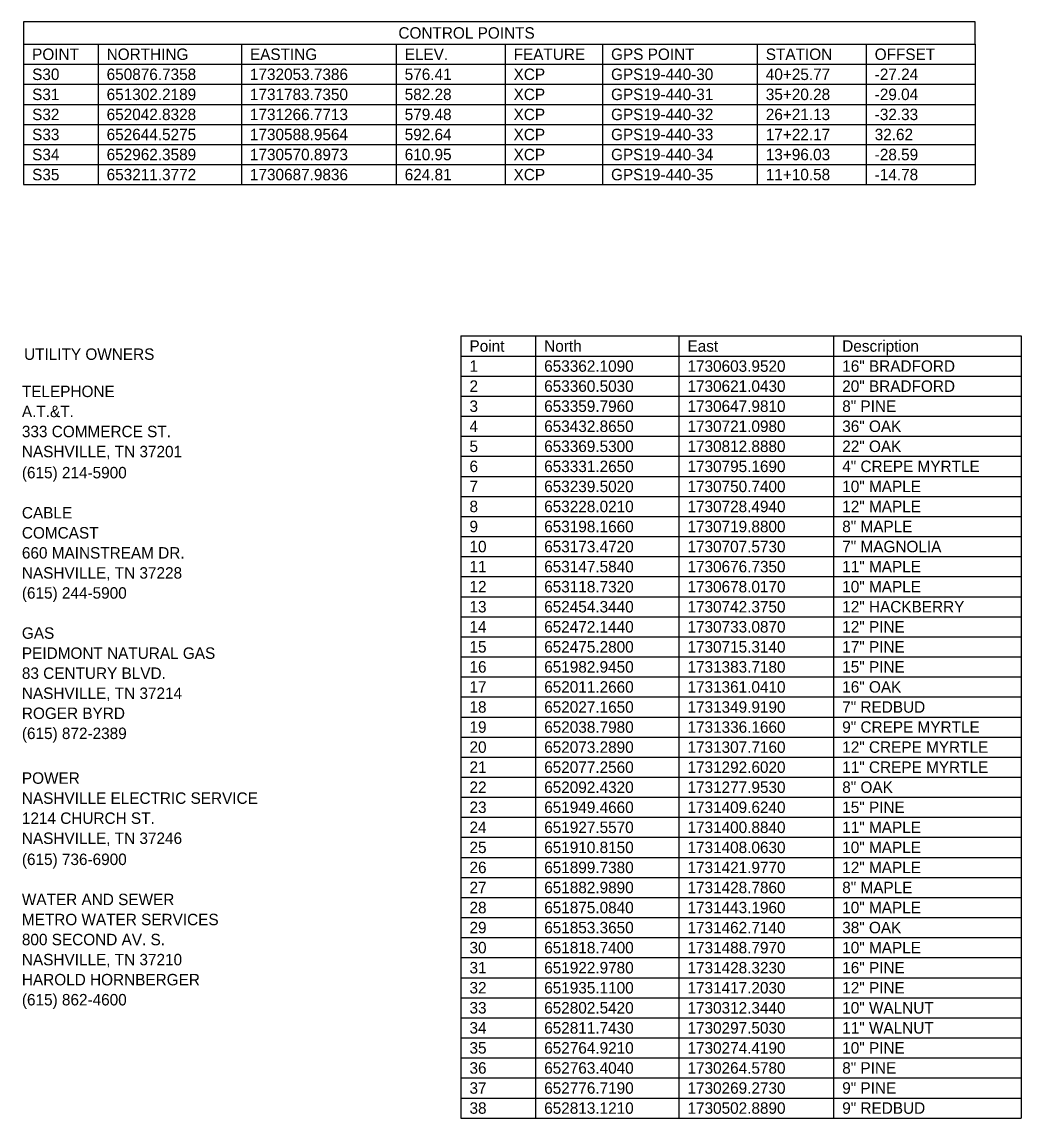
# Model space of a CAD drawing. Extents: x 1729869 to 1735532, y 648588 to 653771.
# Drawn here: x 1732635.3 to 1733071.1, y 650464.1 to 650942.4 of the extents above; entities that cross this region are included whole.
import ezdxf

# ---------------------------------------------------------------- set-up
doc = ezdxf.new("R2010")
doc.units = 0
for name, color, linetype in [('SURVEY - CONTROL with Text', 7, 'Continuous'), ('SURVEY - UTILITIES - Owners', 7, 'Continuous'), ('SURVEY - VEGETATION - Features with Text', 7, 'Continuous')]:
    doc.layers.add(name, color=color, linetype=linetype)

msp = doc.modelspace()

# ---------------------------------------------------------------- linework, layer by layer
at = {"layer": 'SURVEY - CONTROL with Text'}
for p, q in [((1732636.01, 650932.65), (1733051.01, 650932.65)), ((1732636.01, 650932.65), (1732636.01, 650871.4)), ((1732668.51, 650932.65), (1732668.51, 650871.4)), ((1732731.01, 650932.65), (1732731.01, 650871.4)), ((1732798.51, 650932.65), (1732798.51, 650871.4)), ((1732846.01, 650932.65), (1732846.01, 650871.4)), ((1732888.51, 650932.65), (1732888.51, 650871.4)), ((1732956.01, 650932.65), (1732956.01, 650871.4)), ((1733003.51, 650932.65), (1733003.51, 650871.4)), ((1733051.01, 650932.65), (1733051.01, 650871.4)), ((1732636.01, 650923.9), (1733051.01, 650923.9)), ((1732636.01, 650915.15), (1733051.01, 650915.15)), ((1732636.01, 650915.15), (1733051.01, 650915.15)), ((1732636.01, 650915.15), (1733051.01, 650915.15)), ((1732636.01, 650915.15), (1733051.01, 650915.15)), ((1732636.01, 650915.15), (1733051.01, 650915.15)), ((1732636.01, 650915.15), (1733051.01, 650915.15)), ((1732636.01, 650915.15), (1733051.01, 650915.15)), ((1732636.01, 650915.15), (1733051.01, 650915.15)), ((1732636.01, 650906.4), (1733051.01, 650906.4)), ((1732636.01, 650906.4), (1733051.01, 650906.4)), ((1732636.01, 650906.4), (1733051.01, 650906.4)), ((1732636.01, 650906.4), (1733051.01, 650906.4)), ((1732636.01, 650906.4), (1733051.01, 650906.4)), ((1732636.01, 650906.4), (1733051.01, 650906.4)), ((1732636.01, 650906.4), (1733051.01, 650906.4)), ((1732636.01, 650906.4), (1733051.01, 650906.4)), ((1732636.01, 650897.65), (1733051.01, 650897.65)), ((1732636.01, 650897.65), (1733051.01, 650897.65)), ((1732636.01, 650897.65), (1733051.01, 650897.65)), ((1732636.01, 650897.65), (1733051.01, 650897.65)), ((1732636.01, 650897.65), (1733051.01, 650897.65)), ((1732636.01, 650897.65), (1733051.01, 650897.65)), ((1732636.01, 650897.65), (1733051.01, 650897.65)), ((1732636.01, 650897.65), (1733051.01, 650897.65)), ((1732636.01, 650888.9), (1733051.01, 650888.9)), ((1732636.01, 650888.9), (1733051.01, 650888.9)), ((1732636.01, 650888.9), (1733051.01, 650888.9)), ((1732636.01, 650888.9), (1733051.01, 650888.9)), ((1732636.01, 650888.9), (1733051.01, 650888.9)), ((1732636.01, 650888.9), (1733051.01, 650888.9)), ((1732636.01, 650888.9), (1733051.01, 650888.9)), ((1732636.01, 650888.9), (1733051.01, 650888.9)), ((1732636.01, 650880.15), (1733051.01, 650880.15)), ((1732636.01, 650880.15), (1733051.01, 650880.15)), ((1732636.01, 650880.15), (1733051.01, 650880.15)), ((1732636.01, 650880.15), (1733051.01, 650880.15)), ((1732636.01, 650880.15), (1733051.01, 650880.15)), ((1732636.01, 650880.15), (1733051.01, 650880.15)), ((1732636.01, 650880.15), (1733051.01, 650880.15)), ((1732636.01, 650880.15), (1733051.01, 650880.15)), ((1732636.01, 650871.4), (1733051.01, 650871.4)), ((1732636.01, 650871.4), (1733051.01, 650871.4)), ((1732636.01, 650871.4), (1733051.01, 650871.4)), ((1732636.01, 650871.4), (1733051.01, 650871.4)), ((1732636.01, 650871.4), (1733051.01, 650871.4)), ((1732636.01, 650871.4), (1733051.01, 650871.4)), ((1732636.01, 650871.4), (1733051.01, 650871.4)), ((1732636.01, 650871.4), (1733051.01, 650871.4))]:
    msp.add_line(p, q, dxfattribs=at)
msp.add_lwpolyline([(1732636.01, 650932.65), (1733051.01, 650932.65), (1733051.01, 650942.38), (1732636.01, 650942.38)], close=True, dxfattribs=at)
at = {"layer": 'SURVEY - VEGETATION - Features with Text'}
for p, q in [((1732826.77, 650805.34), (1733071.1, 650805.34)), ((1732826.77, 650805.34), (1732826.77, 650464.09)), ((1732859.35, 650805.34), (1732859.35, 650464.09)), ((1732921.85, 650805.34), (1732921.85, 650464.09)), ((1732989.35, 650805.34), (1732989.35, 650464.09)), ((1733071.1, 650805.34), (1733071.1, 650464.09)), ((1732826.77, 650796.59), (1733071.1, 650796.59)), ((1732826.77, 650787.84), (1733056.77, 650787.84)), ((1732826.77, 650787.84), (1733056.77, 650787.84)), ((1732826.77, 650787.84), (1733056.77, 650787.84)), ((1732826.77, 650787.84), (1733071.1, 650787.84)), ((1732826.77, 650779.09), (1733056.77, 650779.09)), ((1732826.77, 650779.09), (1733056.77, 650779.09)), ((1732826.77, 650779.09), (1733056.77, 650779.09)), ((1732826.77, 650779.09), (1733071.1, 650779.09)), ((1732826.77, 650770.34), (1733056.77, 650770.34)), ((1732826.77, 650770.34), (1733056.77, 650770.34)), ((1732826.77, 650770.34), (1733056.77, 650770.34)), ((1732826.77, 650770.34), (1733071.1, 650770.34)), ((1732826.77, 650761.59), (1733056.77, 650761.59)), ((1732826.77, 650761.59), (1733056.77, 650761.59)), ((1732826.77, 650761.59), (1733056.77, 650761.59)), ((1732826.77, 650761.59), (1733071.1, 650761.59)), ((1732826.77, 650752.84), (1733056.77, 650752.84)), ((1732826.77, 650752.84), (1733056.77, 650752.84)), ((1732826.77, 650752.84), (1733056.77, 650752.84)), ((1732826.77, 650752.84), (1733071.1, 650752.84)), ((1732826.77, 650744.09), (1733056.77, 650744.09)), ((1732826.77, 650744.09), (1733056.77, 650744.09)), ((1732826.77, 650744.09), (1733056.77, 650744.09)), ((1732826.77, 650744.09), (1733071.1, 650744.09)), ((1732826.77, 650735.34), (1733056.77, 650735.34)), ((1732826.77, 650735.34), (1733056.77, 650735.34)), ((1732826.77, 650735.34), (1733056.77, 650735.34)), ((1732826.77, 650735.34), (1733071.1, 650735.34)), ((1732826.77, 650726.59), (1733056.77, 650726.59)), ((1732826.77, 650726.59), (1733056.77, 650726.59)), ((1732826.77, 650726.59), (1733056.77, 650726.59)), ((1732826.77, 650726.59), (1733071.1, 650726.59)), ((1732826.77, 650717.84), (1733056.77, 650717.84)), ((1732826.77, 650717.84), (1733056.77, 650717.84)), ((1732826.77, 650717.84), (1733071.1, 650717.84)), ((1732826.77, 650709.09), (1733056.77, 650709.09)), ((1732826.77, 650709.09), (1733056.77, 650709.09)), ((1732826.77, 650709.09), (1733056.77, 650709.09)), ((1732826.77, 650709.09), (1733071.1, 650709.09)), ((1732826.77, 650700.34), (1733056.77, 650700.34)), ((1732826.77, 650700.34), (1733056.77, 650700.34)), ((1732826.77, 650700.34), (1733056.77, 650700.34)), ((1732826.77, 650700.34), (1733071.1, 650700.34)), ((1732826.77, 650691.59), (1733056.77, 650691.59)), ((1732826.77, 650691.59), (1733056.77, 650691.59)), ((1732826.77, 650691.59), (1733056.77, 650691.59)), ((1732826.77, 650691.59), (1733071.1, 650691.59)), ((1732826.77, 650682.84), (1733056.77, 650682.84)), ((1732826.77, 650682.84), (1733056.77, 650682.84)), ((1732826.77, 650682.84), (1733056.77, 650682.84)), ((1732826.77, 650682.84), (1733071.1, 650682.84)), ((1732826.77, 650674.09), (1733056.77, 650674.09)), ((1732826.77, 650674.09), (1733056.77, 650674.09)), ((1732826.77, 650674.09), (1733056.77, 650674.09)), ((1732826.77, 650674.09), (1733071.1, 650674.09)), ((1732826.77, 650665.34), (1733056.77, 650665.34)), ((1732826.77, 650665.34), (1733056.77, 650665.34)), ((1732826.77, 650665.34), (1733056.77, 650665.34)), ((1732826.77, 650665.34), (1733071.1, 650665.34)), ((1732826.77, 650656.59), (1733056.77, 650656.59)), ((1732826.77, 650656.59), (1733056.77, 650656.59)), ((1732826.77, 650656.59), (1733056.77, 650656.59)), ((1732826.77, 650656.59), (1733071.1, 650656.59)), ((1732826.77, 650647.84), (1733056.77, 650647.84)), ((1732826.77, 650647.84), (1733056.77, 650647.84)), ((1732826.77, 650647.84), (1733056.77, 650647.84)), ((1732826.77, 650647.84), (1733071.1, 650647.84)), ((1732826.77, 650639.09), (1733056.77, 650639.09)), ((1732826.77, 650639.09), (1733056.77, 650639.09)), ((1732826.77, 650639.09), (1733056.77, 650639.09)), ((1732826.77, 650639.09), (1733071.1, 650639.09)), ((1732826.77, 650630.34), (1733056.77, 650630.34)), ((1732826.77, 650630.34), (1733056.77, 650630.34)), ((1732826.77, 650630.34), (1733056.77, 650630.34)), ((1732826.77, 650630.34), (1733071.1, 650630.34)), ((1732826.77, 650621.59), (1733056.77, 650621.59)), ((1732826.77, 650621.59), (1733056.77, 650621.59)), ((1732826.77, 650621.59), (1733056.77, 650621.59)), ((1732826.77, 650621.59), (1733071.1, 650621.59)), ((1732826.77, 650612.84), (1733056.77, 650612.84)), ((1732826.77, 650612.84), (1733056.77, 650612.84)), ((1732826.77, 650612.84), (1733056.77, 650612.84)), ((1732826.77, 650612.84), (1733071.1, 650612.84)), ((1732826.77, 650604.09), (1733056.77, 650604.09)), ((1732826.77, 650604.09), (1733056.77, 650604.09)), ((1732826.77, 650604.09), (1733056.77, 650604.09)), ((1732826.77, 650604.09), (1733071.1, 650604.09)), ((1732826.77, 650595.34), (1733056.77, 650595.34)), ((1732826.77, 650595.34), (1733056.77, 650595.34)), ((1732826.77, 650595.34), (1733056.77, 650595.34)), ((1732826.77, 650595.34), (1733071.1, 650595.34)), ((1732826.77, 650586.59), (1733056.77, 650586.59)), ((1732826.77, 650586.59), (1733056.77, 650586.59)), ((1732826.77, 650586.59), (1733056.77, 650586.59)), ((1732826.77, 650586.59), (1733071.1, 650586.59)), ((1732826.77, 650577.84), (1733056.77, 650577.84)), ((1732826.77, 650577.84), (1733056.77, 650577.84)), ((1732826.77, 650577.84), (1733056.77, 650577.84)), ((1732826.77, 650577.84), (1733071.1, 650577.84)), ((1732826.77, 650569.09), (1733056.77, 650569.09)), ((1732826.77, 650569.09), (1733056.77, 650569.09)), ((1732826.77, 650569.09), (1733056.77, 650569.09)), ((1732826.77, 650569.09), (1733071.1, 650569.09)), ((1732826.77, 650560.34), (1733056.77, 650560.34)), ((1732826.77, 650560.34), (1733056.77, 650560.34)), ((1732826.77, 650560.34), (1733056.77, 650560.34)), ((1732826.77, 650560.34), (1733071.1, 650560.34)), ((1732826.77, 650551.59), (1733056.77, 650551.59)), ((1732826.77, 650551.59), (1733056.77, 650551.59)), ((1732826.77, 650551.59), (1733056.77, 650551.59)), ((1732826.77, 650551.59), (1733071.1, 650551.59)), ((1732826.77, 650542.84), (1733056.77, 650542.84)), ((1732826.77, 650542.84), (1733056.77, 650542.84)), ((1732826.77, 650542.84), (1733056.77, 650542.84)), ((1732826.77, 650542.84), (1733071.1, 650542.84)), ((1732826.77, 650534.09), (1733056.77, 650534.09)), ((1732826.77, 650534.09), (1733056.77, 650534.09)), ((1732826.77, 650534.09), (1733056.77, 650534.09)), ((1732826.77, 650534.09), (1733071.1, 650534.09)), ((1732826.77, 650525.34), (1733056.77, 650525.34)), ((1732826.77, 650525.34), (1733056.77, 650525.34)), ((1732826.77, 650525.34), (1733056.77, 650525.34)), ((1732826.77, 650525.34), (1733071.1, 650525.34)), ((1732826.77, 650516.59), (1733056.77, 650516.59)), ((1732826.77, 650516.59), (1733056.77, 650516.59)), ((1732826.77, 650516.59), (1733056.77, 650516.59)), ((1732826.77, 650516.59), (1733071.1, 650516.59)), ((1732826.77, 650507.84), (1733056.77, 650507.84)), ((1732826.77, 650507.84), (1733056.77, 650507.84)), ((1732826.77, 650507.84), (1733056.77, 650507.84)), ((1732826.77, 650507.84), (1733071.1, 650507.84)), ((1732826.77, 650499.09), (1733056.77, 650499.09)), ((1732826.77, 650499.09), (1733056.77, 650499.09)), ((1732826.77, 650499.09), (1733056.77, 650499.09)), ((1732826.77, 650499.09), (1733071.1, 650499.09)), ((1732826.77, 650490.34), (1733056.77, 650490.34)), ((1732826.77, 650490.34), (1733056.77, 650490.34)), ((1732826.77, 650490.34), (1733056.77, 650490.34)), ((1732826.77, 650490.34), (1733071.1, 650490.34)), ((1732826.77, 650481.59), (1733056.77, 650481.59)), ((1732826.77, 650481.59), (1733056.77, 650481.59)), ((1732826.77, 650481.59), (1733056.77, 650481.59)), ((1732826.77, 650481.59), (1733071.1, 650481.59)), ((1732826.77, 650472.84), (1733056.77, 650472.84)), ((1732826.77, 650472.84), (1733056.77, 650472.84)), ((1732826.77, 650472.84), (1733056.77, 650472.84)), ((1732826.77, 650472.84), (1733071.1, 650472.84)), ((1732826.77, 650464.09), (1733056.77, 650464.09)), ((1732826.77, 650464.09), (1733056.77, 650464.09)), ((1732826.77, 650464.09), (1733056.77, 650464.09)), ((1732826.77, 650464.09), (1733071.1, 650464.09))]:
    msp.add_line(p, q, dxfattribs=at)

# ---------------------------------------------------------------- texts
at = {"layer": 'SURVEY - CONTROL with Text'}
for s, p in [('CONTROL POINTS', (1732799.52, 650935.07)), ('POINT', (1732639.76, 650925.77)), ('NORTHING', (1732672.26, 650925.77)), ('EASTING', (1732734.76, 650925.77)), ('ELEV.', (1732802.26, 650925.77)), ('FEATURE', (1732849.76, 650925.77)), ('GPS POINT', (1732892.26, 650925.77)), ('STATION', (1732959.76, 650925.77)), ('OFFSET', (1733007.26, 650925.77)), ('S30', (1732639.76, 650917.02)), ('650876.7358', (1732672.26, 650917.02)), ('1732053.7386', (1732734.76, 650917.02)), ('576.41', (1732802.26, 650917.02)), ('XCP', (1732849.76, 650917.02)), ('GPS19-440-30', (1732892.26, 650917.02)), ('40+25.77', (1732959.76, 650917.02)), ('-27.24', (1733007.26, 650917.02)), ('S31', (1732639.76, 650908.27)), ('651302.2189', (1732672.26, 650908.27)), ('1731783.7350', (1732734.76, 650908.27)), ('582.28', (1732802.26, 650908.27)), ('XCP', (1732849.76, 650908.27)), ('GPS19-440-31', (1732892.26, 650908.27)), ('35+20.28', (1732959.76, 650908.27)), ('-29.04', (1733007.26, 650908.27)), ('S32', (1732639.76, 650899.52)), ('652042.8328', (1732672.26, 650899.52)), ('1731266.7713', (1732734.76, 650899.52)), ('579.48', (1732802.26, 650899.52)), ('XCP', (1732849.76, 650899.52)), ('GPS19-440-32', (1732892.26, 650899.52)), ('26+21.13', (1732959.76, 650899.52)), ('-32.33', (1733007.26, 650899.52)), ('S33', (1732639.76, 650890.77)), ('652644.5275', (1732672.26, 650890.77)), ('1730588.9564', (1732734.76, 650890.77)), ('592.64', (1732802.26, 650890.77)), ('XCP', (1732849.76, 650890.77)), ('GPS19-440-33', (1732892.26, 650890.77)), ('17+22.17', (1732959.76, 650890.77)), ('32.62', (1733007.26, 650890.77)), ('S34', (1732639.76, 650882.02)), ('652962.3589', (1732672.26, 650882.02)), ('1730570.8973', (1732734.76, 650882.02)), ('610.95', (1732802.26, 650882.02)), ('XCP', (1732849.76, 650882.02)), ('GPS19-440-34', (1732892.26, 650882.02)), ('13+96.03', (1732959.76, 650882.02)), ('-28.59', (1733007.26, 650882.02)), ('S35', (1732639.76, 650873.27)), ('653211.3772', (1732672.26, 650873.27)), ('1730687.9836', (1732734.76, 650873.27)), ('624.81', (1732802.26, 650873.27)), ('XCP', (1732849.76, 650873.27)), ('GPS19-440-35', (1732892.26, 650873.27)), ('11+10.58', (1732959.76, 650873.27)), ('-14.78', (1733007.26, 650873.27))]:
    msp.add_text(s, height=5, dxfattribs=at).set_placement(p)
at = {"layer": 'SURVEY - UTILITIES - Owners'}
for s, p in [('UTILITY OWNERS', (1732636.24, 650794.91)), ('TELEPHONE', (1732635.29, 650778.67)), ('A.T.&T.', (1732635.29, 650769.92)), ('333 COMMERCE ST.', (1732635.29, 650761.17)), ('NASHVILLE, TN 37201', (1732635.29, 650752.42)), ('(615) 214-5900', (1732635.29, 650743.21)), ('CABLE', (1732635.29, 650725.71)), ('COMCAST', (1732635.29, 650716.96)), ('660 MAINSTREAM DR.', (1732635.29, 650708.21)), ('NASHVILLE, TN 37228', (1732635.29, 650699.46)), ('(615) 244-5900', (1732635.29, 650690.71)), ('GAS', (1732635.29, 650673.21)), ('PEIDMONT NATURAL GAS', (1732635.29, 650664.46)), ('83 CENTURY BLVD.', (1732635.29, 650655.71)), ('NASHVILLE, TN 37214', (1732635.29, 650646.96)), ('ROGER BYRD', (1732635.29, 650638.21)), ('(615) 872-2389', (1732635.29, 650629.46)), ('POWER', (1732635.29, 650609.94)), ('NASHVILLE ELECTRIC SERVICE', (1732635.29, 650601.19)), ('1214 CHURCH ST.', (1732635.29, 650592.44)), ('NASHVILLE, TN 37246', (1732635.29, 650583.69)), ('(615) 736-6900', (1732635.29, 650574.49)), ('WATER AND SEWER', (1732635.29, 650556.99)), ('METRO WATER SERVICES', (1732635.29, 650548.24)), ('800 SECOND AV. S.', (1732635.29, 650539.49)), ('NASHVILLE, TN 37210', (1732635.29, 650530.74)), ('HAROLD HORNBERGER', (1732635.29, 650521.99)), ('(615) 862-4600', (1732635.29, 650513.24))]:
    msp.add_text(s, height=5, dxfattribs=at).set_placement(p)
at = {"layer": 'SURVEY - VEGETATION - Features with Text'}
for s, p in [('Point', (1732830.52, 650798.46)), ('North', (1732863.1, 650798.46)), ('East', (1732925.6, 650798.46)), ('Description', (1732993.1, 650798.46)), ('1', (1732830.52, 650789.71)), ('653362.1090', (1732863.1, 650789.71)), ('1730603.9520', (1732925.6, 650789.71)), ('16" BRADFORD', (1732993.1, 650789.71)), ('2', (1732830.52, 650780.96)), ('653360.5030', (1732863.1, 650780.96)), ('1730621.0430', (1732925.6, 650780.96)), ('20" BRADFORD', (1732993.1, 650780.96)), ('3', (1732830.52, 650772.21)), ('653359.7960', (1732863.1, 650772.21)), ('1730647.9810', (1732925.6, 650772.21)), ('8" PINE', (1732993.1, 650772.21)), ('4', (1732830.52, 650763.46)), ('653432.8650', (1732863.1, 650763.46)), ('1730721.0980', (1732925.6, 650763.46)), ('36" OAK', (1732993.1, 650763.46)), ('653369.5300', (1732863.1, 650754.71)), ('1730812.8880', (1732925.6, 650754.71)), ('22" OAK', (1732993.1, 650754.71)), ('5', (1732830.52, 650754.71)), ('6', (1732830.52, 650745.96)), ('653331.2650', (1732863.1, 650745.96)), ('1730795.1690', (1732925.6, 650745.96)), ('4" CREPE MYRTLE', (1732993.1, 650745.96)), ('7', (1732830.52, 650737.21)), ('653239.5020', (1732863.1, 650737.21)), ('1730750.7400', (1732925.6, 650737.21)), ('10" MAPLE', (1732993.1, 650737.21)), ('8', (1732830.52, 650728.46)), ('653228.0210', (1732863.1, 650728.46)), ('1730728.4940', (1732925.6, 650728.46)), ('12" MAPLE', (1732993.1, 650728.46)), ('9', (1732830.52, 650719.71)), ('653198.1660', (1732863.1, 650719.71)), ('1730719.8800', (1732925.6, 650719.71)), ('8" MAPLE', (1732993.1, 650719.71)), ('10', (1732830.52, 650710.96)), ('653173.4720', (1732863.1, 650710.96)), ('1730707.5730', (1732925.6, 650710.96)), ('7" MAGNOLIA', (1732993.1, 650710.96)), ('11', (1732830.52, 650702.21)), ('653147.5840', (1732863.1, 650702.21)), ('1730676.7350', (1732925.6, 650702.21)), ('11" MAPLE', (1732993.1, 650702.21)), ('12', (1732830.52, 650693.46)), ('653118.7320', (1732863.1, 650693.46)), ('1730678.0170', (1732925.6, 650693.46)), ('10" MAPLE', (1732993.1, 650693.46)), ('13', (1732830.52, 650684.71)), ('652454.3440', (1732863.1, 650684.71)), ('1730742.3750', (1732925.6, 650684.71)), ('12" HACKBERRY', (1732993.1, 650684.71)), ('14', (1732830.52, 650675.96)), ('652472.1440', (1732863.1, 650675.96)), ('1730733.0870', (1732925.6, 650675.96)), ('12" PINE', (1732993.1, 650675.96)), ('15', (1732830.52, 650667.21)), ('652475.2800', (1732863.1, 650667.21)), ('1730715.3140', (1732925.6, 650667.21)), ('17" PINE', (1732993.1, 650667.21)), ('16', (1732830.52, 650658.46)), ('651982.9450', (1732863.1, 650658.46)), ('1731383.7180', (1732925.6, 650658.46)), ('15" PINE', (1732993.1, 650658.46)), ('17', (1732830.52, 650649.71)), ('652011.2660', (1732863.1, 650649.71)), ('1731361.0410', (1732925.6, 650649.71)), ('16" OAK', (1732993.1, 650649.71)), ('18', (1732830.52, 650640.96)), ('652027.1650', (1732863.1, 650640.96)), ('1731349.9190', (1732925.6, 650640.96)), ('7" REDBUD', (1732993.1, 650640.96)), ('19', (1732830.52, 650632.21)), ('652038.7980', (1732863.1, 650632.21)), ('1731336.1660', (1732925.6, 650632.21)), ('9" CREPE MYRTLE', (1732993.1, 650632.21)), ('20', (1732830.52, 650623.46)), ('652073.2890', (1732863.1, 650623.46)), ('1731307.7160', (1732925.6, 650623.46)), ('12" CREPE MYRTLE', (1732993.1, 650623.46)), ('21', (1732830.52, 650614.71)), ('652077.2560', (1732863.1, 650614.71)), ('1731292.6020', (1732925.6, 650614.71)), ('11" CREPE MYRTLE', (1732993.1, 650614.71)), ('22', (1732830.52, 650605.96)), ('652092.4320', (1732863.1, 650605.96)), ('1731277.9530', (1732925.6, 650605.96)), ('8" OAK', (1732993.1, 650605.96)), ('23', (1732830.52, 650597.21)), ('651949.4660', (1732863.1, 650597.21)), ('1731409.6240', (1732925.6, 650597.21)), ('15" PINE', (1732993.1, 650597.21)), ('24', (1732830.52, 650588.46)), ('651927.5570', (1732863.1, 650588.46)), ('1731400.8840', (1732925.6, 650588.46)), ('11" MAPLE', (1732993.1, 650588.46)), ('25', (1732830.52, 650579.71)), ('651910.8150', (1732863.1, 650579.71)), ('1731408.0630', (1732925.6, 650579.71)), ('10" MAPLE', (1732993.1, 650579.71)), ('26', (1732830.52, 650570.96)), ('651899.7380', (1732863.1, 650570.96)), ('1731421.9770', (1732925.6, 650570.96)), ('12" MAPLE', (1732993.1, 650570.96)), ('27', (1732830.52, 650562.21)), ('651882.9890', (1732863.1, 650562.21)), ('1731428.7860', (1732925.6, 650562.21)), ('8" MAPLE', (1732993.1, 650562.21)), ('28', (1732830.52, 650553.46)), ('651875.0840', (1732863.1, 650553.46)), ('1731443.1960', (1732925.6, 650553.46)), ('10" MAPLE', (1732993.1, 650553.46)), ('29', (1732830.52, 650544.71)), ('651853.3650', (1732863.1, 650544.71)), ('1731462.7140', (1732925.6, 650544.71)), ('38" OAK', (1732993.1, 650544.71)), ('30', (1732830.52, 650535.96)), ('651818.7400', (1732863.1, 650535.96)), ('1731488.7970', (1732925.6, 650535.96)), ('10" MAPLE', (1732993.1, 650535.96)), ('31', (1732830.52, 650527.21)), ('651922.9780', (1732863.1, 650527.21)), ('1731428.3230', (1732925.6, 650527.21)), ('16" PINE', (1732993.1, 650527.21)), ('32', (1732830.52, 650518.46)), ('651935.1100', (1732863.1, 650518.46)), ('1731417.2030', (1732925.6, 650518.46)), ('12" PINE', (1732993.1, 650518.46)), ('33', (1732830.52, 650509.71)), ('652802.5420', (1732863.1, 650509.71)), ('1730312.3440', (1732925.6, 650509.71)), ('10" WALNUT', (1732993.1, 650509.71)), ('34', (1732830.52, 650500.96)), ('652811.7430', (1732863.1, 650500.96)), ('1730297.5030', (1732925.6, 650500.96)), ('11" WALNUT', (1732993.1, 650500.96)), ('35', (1732830.52, 650492.21)), ('652764.9210', (1732863.1, 650492.21)), ('1730274.4190', (1732925.6, 650492.21)), ('10" PINE', (1732993.1, 650492.21)), ('36', (1732830.52, 650483.46)), ('652763.4040', (1732863.1, 650483.46)), ('1730264.5780', (1732925.6, 650483.46)), ('8" PINE', (1732993.1, 650483.46)), ('37', (1732830.52, 650474.71)), ('652776.7190', (1732863.1, 650474.71)), ('1730269.2730', (1732925.6, 650474.71)), ('9" PINE', (1732993.1, 650474.71)), ('38', (1732830.52, 650465.96)), ('652813.1210', (1732863.1, 650465.96)), ('1730502.8890', (1732925.6, 650465.96)), ('9" REDBUD', (1732993.1, 650465.96))]:
    msp.add_text(s, height=5, rotation=360, dxfattribs=at).set_placement(p)

doc.saveas('drawing.dxf')
